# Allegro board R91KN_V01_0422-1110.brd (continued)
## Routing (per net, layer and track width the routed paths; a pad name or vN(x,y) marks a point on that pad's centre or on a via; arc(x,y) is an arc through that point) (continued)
M_MAA1: length 107.4
  TOP w0.097: 137.37,69.38 137.53,69.38 137.66,69.25 137.66,69 137.57,68.92 137.22,68.92 137.02,68.72 137.02,68.43 137.18,68.28 137.18,68.07 137.02,67.92 137.02,67.63 137.22,67.43 137.42,67.43 137.64,67.22 137.64,67.22 137.95,66.91 138.36,66.91 138.95,66.32 139.79,66.32 139.91,66.21 139.91,65.06 139.92,65.04 139.92,65.03 139.79,64.91 138.43,64.91 138.2,64.68 138.2,64.54 138.2,64.53 138.2,64.28 138.19,64.28 138.19,64.19 137.8,63.8 v1(137.73,63.8) 137.73,63.73 137.56,63.56 137.1,63.56 136.78,63.24 136.71,63.18 136.22,63.18 135.12,62.35 134.99,62.29 134.91,62.23 133.77,62.23 133.24,62.17 132.7,62.11 132.48,61.89 132.35,61.77 130.93,60.17 130.93,56.99 130.97,56.89 130.97,56.43 v1(131.26,56.13) 131.26,56.74 131.39,56.87 131.48,56.87 131.69,56.66 131.69,56.09 131.81,55.96 132,55.96 132.11,55.85 132.23,55.85 132.3,55.92 132.42,55.92 132.51,55.83 132.51,55.71 132.44,55.64 132.44,55.44 132.5,55.38 132.61,55.38 132.72,55.5 132.85,55.5 132.94,55.41 132.94,55.28 132.77,55.12 132.77,54.99 132.86,54.9 132.98,54.9 133.15,55.07 133.27,55.07 133.36,54.98 133.36,54.86 132.99,54.49 132.99,54.37 133.08,54.28 133.21,54.28 133.61,54.68 133.73,54.68 133.82,54.6 133.82,54.47 133.72,54.37 133.72,54.24 133.72,54.17 133.91,53.98 134.24,53.98 134.43,53.8 134.66,53.8 134.66,53.57 135.83,52.4 136.46,52.4 137.2,51.66 137.86,51.66 137.98,51.54 137.98,51.52 138.08,51.42 138.31,51.42 138.41,51.33 v1(138.41,51.29) ; v1(131.87,50.35) 131.93,50.42 132.49,50.42 132.54,50.37 132.54,50.21 132.62,50.13 132.7,50.13 132.71,50.12 132.75,50.12 132.84,50.21 132.84,50.38 132.93,50.48 133.07,50.48 133.16,50.38 133.16,49.85 133.21,49.8 133.43,49.8 133.55,49.91 133.88,49.91 134.04,49.76 134.04,49.76 134.12,49.68 134.12,49.52 134.5,49.14 134.5,48.96 134.51,48.95 134.51,48.67 134.5,48.67 134.5,48.16 134.51,48.16 134.51,47.88 134.5,47.87 134.5,47.77 134.4,47.67 134.06,47.67 133.92,47.54 133.92,47.35 134.06,47.22 134.16,47.22
  TOP w0.1: v1(134.68,53.8) 134.66,53.8
  TOP w0.2: U1.J20 96.15,55.9 v1(96.52,55.52)
  BOTTOM w0.097: v1(137.73,63.8) 137.61,63.67 136.54,63.67 136.51,63.65 136.19,63.65 135.95,63.88 135.95,63.94 135.62,64.27 135.62,65.43 135.09,65.97 135.09,68.14 134.51,68.72 134.51,68.72 134.31,68.92 133.98,68.92 133.85,69.04 133.85,69.24 133.98,69.36 134.16,69.36 U402.P7 ; 137.37,47.22 137.37,47.17 137.48,47.06 137.54,47.06 137.55,47.05 137.72,47.05 137.82,47.15 137.82,47.36 137.84,47.38 137.84,47.39 137.94,47.49 137.94,47.75 137.81,47.87 137.71,47.87 137.51,47.67 137.22,47.67 137.02,47.87 137.02,48.96 137.08,49.01 137.08,49.24 136.97,49.35 136.97,49.45 137.05,49.53 137.15,49.53 137.31,49.36 137.43,49.36 137.51,49.43 137.51,49.53 137.38,49.67 137.38,49.79 137.46,49.88 137.59,49.88 137.71,49.75 137.84,49.75 137.93,49.84 137.93,49.97 137.8,50.09 137.8,50.22 137.89,50.3 138.01,50.3 138.14,50.18 138.26,50.18 138.41,50.32 v1(138.41,51.29) ; v1(134.68,53.8) 134.66,53.8 134.66,53.43 131.87,50.64 v1(131.87,50.35)
  BOTTOM w0.1: 101.51,54.15 101.31,54.15 101.08,54.38 101.08,54.61 100.95,54.73 100.74,54.73 100.62,54.61 100.62,54.38 100.49,54.26 100.3,54.26 100.17,54.38 100.17,54.62 100.05,54.74 99.85,54.74 99.72,54.62 99.72,54.38 99.6,54.26 99.38,54.26 99.32,54.2 98.98,54.2 98.4,54.78 96.25,54.78 96.13,54.91 96.13,55.4 96.25,55.52 v1(96.52,55.52)
  BOTTOM w0.2: v1(131.26,56.13) 131.26,56.14 131.08,56.14 130.78,55.84 130.01,55.84 128.03,53.85 128.02,53.85 127.93,53.76 127.54,53.76 127.45,53.85 124.69,53.85 124.37,54.17 104.39,54.17 104.27,54.29 104.27,54.97 103.9,55.34 103.73,55.34 103.6,55.22 103.6,54.28 103.48,54.16 103.09,54.16 102.97,54.28 v4(102.97,54.7) 102.97,55.26 102.84,55.38 102.68,55.38 102.26,54.96 102.26,54.27 102.14,54.15 101.51,54.15
M_MAA2: length 111.7
  TOP w0.097: v1(131.51,66.61) 131.53,66.59 131.57,66.59 131.73,66.43 133.53,66.43 133.96,66.86 133.96,67.08 134.51,67.62 134.51,68.72 134.31,68.92 133.82,68.92 133.7,69.04 133.7,69.23 133.71,69.23 133.71,69.52 133.7,69.52 133.7,69.71 133.82,69.83 134.04,69.83 134.16,69.71 U401.P3 ; 137.37,47.22 137.34,47.22 137.22,47.33 137.22,47.49 137.35,47.62 137.48,47.62 137.69,47.41 137.81,47.41 138,47.6 138,47.7 137.82,47.87 137.82,48.16 138,48.34 138,48.49 137.82,48.67 137.82,48.96 137.88,49.02 137.88,49.03 137.97,49.12 137.98,49.12 138.02,49.16 138.22,49.16 138.3,49.23 138.62,49.23 138.82,49.44 138.82,49.52 139.46,50.15 139.46,50.96 139.83,51.33 140.23,51.33 140.32,51.42 140.32,51.57 140.23,51.66 139.61,51.66 139.52,51.76 139.52,51.89 139.61,51.98 140.27,51.98 140.32,52.03 140.32,52.22 140.27,52.27 139.5,52.27 v1(139.4,52.38) 139.4,52.4 139.53,52.52 139.82,52.52 139.91,52.61 139.91,52.73 139.82,52.82 139.36,52.82 139.28,52.9 139.28,53 139.36,53.08 139.78,53.08 139.87,53.17 139.87,53.29 139.78,53.38 139.42,53.38 139.34,53.46 139.34,53.57 139.42,53.65 139.81,53.65 139.9,53.74 139.9,53.85 139.8,53.95 139.16,53.95 139.03,54.08 139.03,54.11 139.27,54.35 139.27,54.48 139.18,54.57 139.06,54.57 138.82,54.33 138.69,54.33 138.61,54.41 138.61,54.54 138.85,54.78 138.85,54.9 138.76,54.99 138.63,54.99 138.39,54.75 138.28,54.75 138.18,54.84 138.18,54.93 138.31,55.05 138.31,55.06 138.41,55.17 138.41,55.27 138.34,55.34 138.23,55.34 138.06,55.17 137.85,55.17 137.76,55.26 137.76,55.39 137.78,55.41 137.78,55.53 137.69,55.62 137.56,55.62 137.55,55.6 137.42,55.6 137.33,55.69 137.33,55.81 137.35,55.83 137.35,55.95 137.26,56.04 137.14,56.04 137.12,56.02 137,56.02 136.91,56.11 136.91,56.23 136.93,56.25 136.93,56.38 136.84,56.47 136.55,56.47 v1(135.84,57.19) 135.84,57.47 135.44,57.87 135.44,57.99 134.87,58.57 134.87,59.67 v1(134.85,59.69)
  TOP w0.17: U1.H23 97.15,53.8 97.35,54 v1(97.35,54.3)
  BOTTOM w0.097: v1(139.4,52.38) 138.61,52.38 v4(138.5,52.27) 138.5,52.27 138.49,52.27 137.58,51.35 135.53,51.35 135.45,51.25 135.14,50.95 135.08,50.8 134.83,47.88 134.16,47.22 ; 137.37,69.38 138.01,69.78 139.84,69.78 140.8,68.81 140.8,61.83 138.38,59.41 135.96,59.41 135.89,59.49 135.05,59.49 v1(134.85,59.69) 135.04,59.88 135.57,59.88 135.8,60.11 135.8,60.45 135.51,60.73 135.4,60.73 131.51,64.62 v1(131.51,66.61)
  BOTTOM w0.1: 100.44,53.77 100.4,53.8 96.81,53.8 96.72,53.9 96.72,54.2 96.81,54.3 v1(97.35,54.3)
  BOTTOM w0.2: v1(135.84,57.19) 135.73,57.28 135.64,57.28 135.18,57.14 134.85,57.08 134.7,57.03 134.33,56.98 133.03,55.67 133.03,55.67 131.91,55.67 131.59,55.35 131.24,55.35 131.06,55.17 131,55.17 131,55.17 130.29,55.17 128.34,53.21 128.34,53.21 128.31,53.19 128.3,53.19 128.21,53.09 127.26,53.09 127.17,53.19 124.41,53.19 124.39,53.2 124.34,53.2 124.07,53.46 100.74,53.46 100.44,53.77
M_MAA3: length 114.4
  TOP w0.097: v1(137.79,64.5) 137.78,64.5 137.63,64.27 137.25,63.89 137,63.78 136.62,63.41 136.13,63.41 135,62.55 134.85,62.49 134.83,62.47 133.76,62.47 v1(132.33,62.3) 130.69,60.25 130.69,56.96 130.7,56.92 130.73,56.84 130.73,56.66 130.71,56.63 130.71,56.19 v1(131.52,54.9) 131.75,54.9 131.88,55.02 131.88,55.23 131.75,55.36 131.55,55.36 131.44,55.47 131.44,55.62 131.55,55.73 131.9,55.73 132.15,55.48 132.15,55.02 132.28,54.9 132.5,54.9 132.59,54.81 132.59,54.67 132.5,54.58 132.09,54.58 131.98,54.47 131.98,54.34 132.11,54.21 132.79,54.21 132.92,54.09 132.92,54.08 133.18,53.82 133.32,53.82 v1(133.41,53.91) 133.58,53.75 134.15,53.75 135.73,52.16 136.06,52.16 136.41,52.16 137.12,51.45 137.7,51.45 137.81,51.35 138,51.15 138,51.12 138.04,51.09 138.04,50.96 138.11,50.89 138.76,50.89 138.83,50.82 138.83,50.73 138.76,50.66 138.42,50.66 138.37,50.61 138.37,50.47 138.43,50.41 138.62,50.41 138.69,50.34 138.69,50.23 138.29,49.83 138.2,49.83 138.12,49.92 138.12,49.92 138,50.04 137.87,50.04 137.8,49.98 137.8,49.95 137.7,49.84 137.7,49.72 137.34,49.36 136.92,49.36 136.82,49.27 136.82,47.95 137.02,47.75 137.02,46.89 137.15,46.77 137.48,46.77 137.61,46.89 137.61,46.93 137.73,47.05 137.84,47.05 138.02,46.87 138.5,46.87 138.63,46.75 138.63,46.56 138.62,46.56 138.62,46.27 138.63,46.27 138.63,46.14 138.5,46.02 137.84,46.02 137.71,46.14 137.71,46.29 137.84,46.41 U202.N2 ; v1(131.26,69.91) 131.44,69.73 133.07,69.73 133.37,70.03 133.37,70.17
  TOP w0.17: v1(97.35,53.4) 97.65,53.4 97.75,53.5 U1.G23
  BOTTOM w0.097: U402.N2 138.08,70.09 137.96,70.03 137.79,69.94 137.49,69.81 137.24,69.73 137.02,69.52 137.02,67.63 137.03,67.63 137.22,67.43 137.29,67.43 137.29,67.37 138.39,66.27 138.39,66.03 138.39,66.03 138.39,65.63 138.39,65.63 138.39,65.47 138.27,65.35 138.27,65.35 137.79,64.88 v1(137.79,64.5) ; v1(131.26,69.91) 130.95,69.91 130.13,69.09 130.13,68.62 130.34,68.41 130.34,67.45 130.21,67.31 130.21,66.89 130.48,66.62 130.48,65.81 130.28,65.61 130.28,64.31 131.68,62.91 131.76,62.91 131.99,62.68 131.99,62.41 132.1,62.3 v1(132.33,62.3) ; v1(133.41,53.91) 133.39,53.9 132.07,53.9 131.75,53.56 131.5,53.31 131.5,53.31 131.37,53.19 131.37,52.23 130.61,51.48 129.84,50.7 129.84,50.53 129.62,50.31 129.62,49.97 130.1,49.48 130.1,49.03 130.44,48.69 130.44,48.38 130.31,48.24 130.31,47.7 130.44,47.57 130.44,46.82 130.95,46.31 131.29,46.31 131.52,46.55 131.52,46.57 131.81,46.87 133.7,46.87 133.82,46.74 133.82,46.56 133.82,46.56 133.82,46.27 133.99,46.1 133.99,45.96 133.9,45.86 133.61,45.86 133.51,45.96 133.47,45.96 133.37,46.06 133.37,46.41
  BOTTOM w0.2: v1(97.35,53.4) 97.48,53.53 99.48,53.53 99.7,53.31 99.7,52.63 99.79,52.55 100.33,52.55 100.49,52.7 v4(100.49,52.86) 100.49,53.01 100.58,53.1 101.02,53.1 101.14,52.98 101.14,52.67 101.27,52.55 101.84,52.55 102.14,52.84 102.14,53 102.26,53.12 114.39,53.12 114.49,53.02 114.49,52.85 114.59,52.76 114.99,52.76 115.09,52.85 115.09,53.02 115.19,53.12 115.59,53.12 115.69,53.02 115.69,52.85 115.79,52.76 116.19,52.76 116.29,52.85 116.29,53.02 116.39,53.12 116.79,53.12 116.89,53.02 116.89,52.85 116.99,52.76 117.4,52.76 117.5,52.85 117.5,53.05 117.58,53.12 118.03,53.12 118.1,53.05 118.1,52.85 118.2,52.76 118.59,52.76 118.69,52.85 118.69,53.02 118.79,53.12 119.19,53.12 119.29,53.02 119.29,52.85 119.39,52.76 119.79,52.76 119.91,52.87 119.91,53.02 120.01,53.12 120.41,53.12 120.51,53.02 120.51,52.87 120.61,52.77 120.99,52.77 121.09,52.87 121.09,53.02 121.19,53.12 121.59,53.12 121.69,53.02 121.69,52.85 121.79,52.76 122.06,52.76 122.18,52.88 122.18,53.01 122.3,53.13 122.67,53.13 122.73,53.07 122.73,52.88 122.85,52.76 123.16,52.76 123.29,52.88 123.29,52.98 123.41,53.1 123.96,53.1 124.2,52.87 124.25,52.87 124.27,52.85 124.38,52.85 124.38,52.85 127.03,52.85 127.12,52.76 128.34,52.76 128.44,52.85 128.45,52.85 130.44,54.84 131.45,54.84 131.52,54.9 v1(131.52,54.9)
M_MAA4: length 116.2
  TOP w0.097: U401.P8 138.13,69.34 138.13,69.09 138.25,68.97 140.39,68.97 141.06,68.31 141.06,65.95 141.5,65.51 141.5,61.44 141.5,61.44 141.5,61.24 141.5,61.24 141.5,61.11 141.37,60.98 141.24,60.98 141.24,60.98 v4(139.37,60.98) 137.97,60.98 137.84,60.86 v1(137.84,60.42) 137.81,60.39 137.81,59.88 137.72,59.78 137.41,59.78 137.28,59.66 137.28,59.51 137.37,59.42 138.05,59.42 138.05,59.41 138.28,59.41 138.38,59.32 138.38,59.21 138.29,59.12 137.37,59.12 137.28,59.03 137.28,58.91 137.37,58.82 138.3,58.82 138.39,58.73 138.39,58.03 138.26,57.91 137.41,57.91 137.28,57.78 137.28,57.47 137.34,57.41 137.37,57.41 137.74,57.03 137.74,56.5 138.06,56.18 139.43,56.18 v1(140.03,55.58) ; v1(131.27,47.34) 131.75,46.87 133.01,46.87 133.37,47.22
  TOP w0.1: v3(137.28,57.41) 137.34,57.41
  TOP w0.17: v1(98.1,54.3) 98.12,53.62 98.02,53.45 97.99,53.38 U1.G24
  BOTTOM w0.097: v1(137.84,60.42) 137.7,60.27 136.8,60.27 135.88,61.2 135.6,61.2 132.04,64.75 132.04,66.24 132.2,66.4 132.2,66.8 131.93,67.06 131.93,67.41 132.11,67.59 132.11,67.8 132.42,68.12 132.67,68.12 132.91,68.36 132.91,69.44 133.03,69.57 133.24,69.57 133.37,69.44 133.37,69.38 ; 138.16,47.22 138.16,46.87 138.27,46.76 138.47,46.76 138.63,46.92 138.63,47.07 138.62,47.07 138.62,47.36 138.62,47.36 138.62,47.48 138.77,47.63 139.37,47.63 139.39,47.62 139.72,47.62 139.74,47.63 139.99,47.63 140.08,47.54 140.08,46.45 140.21,46.33 140.47,46.33 140.6,46.45 140.6,47.38 140.94,47.73 140.94,51.67 140.97,51.69 140.97,52.4 141.59,53.02 141.59,53.48 141.68,53.56 142.07,53.56 142.16,53.65 142.16,53.78 142.07,53.86 141.68,53.86 141.59,53.95 141.59,54.08 141.68,54.16 142.05,54.16 142.14,54.25 142.14,54.38 142.05,54.46 141.68,54.46 141.59,54.55 141.59,54.99 140.97,55.6 140.05,55.6 v1(140.03,55.58) 140.03,55.58 136.93,55.58 135.73,54.38 135.73,54.17 132.44,50.87 132.44,50.28 131.59,49.44 131.59,49.18 131.42,49.01 131.42,47.49 v1(131.27,47.34)
  BOTTOM w0.1: 100.75,54.02 100.32,54.02 100.31,54 98.94,54 v1(98.1,54.3)
  BOTTOM w0.2: v3(137.28,57.41) 137.22,57.38 136.95,57.3 136.37,57.3 136.03,57.63 135.65,57.63 135.1,57.47 134.77,57.4 134.62,57.36 134.18,57.29 133.06,56.17 131.94,56.17 131.45,55.69 131.1,55.69 130.92,55.51 130.86,55.51 130.86,55.51 130.16,55.51 128.17,53.52 128.16,53.52 128.06,53.42 127.41,53.42 127.31,53.52 124.54,53.52 124.53,53.53 124.47,53.53 124.21,53.8 101.29,53.8 100.75,54.02
M_MAA5: length 114.1
  TOP w0.097: 133.37,69.38 133.03,69.16 132.78,69.11 132.7,69.05 132.17,68.94 131.84,68.94 131.8,68.98 v1(131.44,68.98) ; 138.16,47.22 138.16,47.42 138.2,47.45 138.2,47.53 138.32,47.66 138.55,47.66 138.68,47.53 138.68,47.41 138.62,47.36 138.62,47.07 138.64,47.06 138.64,47.02 138.79,46.87 138.87,46.87 138.92,46.81 140.51,46.81 140.61,46.91 140.61,47.04 140.51,47.14 140.06,47.14 139.97,47.24 139.97,47.38 139.96,47.39 140.06,47.49 140.87,47.49 140.96,47.58 140.96,47.7 140.87,47.79 140.08,47.79 140,47.88 140,48 140.08,48.09 140.87,48.09 140.96,48.18 140.96,54.21 140.87,54.3 140.4,54.3 140.31,54.39 140.31,54.51 140.4,54.6 140.87,54.6 140.96,54.69 140.96,54.92 v1(140.79,55.09) 140.96,55.26 140.96,56.41 140.75,56.62 140.05,56.62 139.95,56.72 139.95,57.09 139.83,57.2 139.67,57.2 139.55,57.09 139.55,56.72 139.45,56.62 v1(138.19,56.62) 138.62,57.05 138.62,59.41 v1(138.22,59.81)
  TOP w0.17: v1(97.35,52.6) U1.H24
  BOTTOM w0.097: U402.P2 138.16,69.24 138.28,69.12 138.53,69.12 138.69,68.97 140.18,68.97 140.31,68.85 140.31,68.64 140.18,68.51 140.03,68.51 139.94,68.42 139.94,68.3 140.03,68.21 140.39,68.21 140.48,68.12 140.48,68 140.39,67.91 140.2,67.91 140.11,67.82 140.11,67.7 140.2,67.61 140.39,67.61 140.48,67.52 140.48,67.4 140.39,67.31 139.94,67.31 139.85,67.22 139.85,67.1 139.94,67.01 140.39,67.01 140.48,66.92 140.48,66.72 140.39,66.64 140.07,66.64 139.98,66.55 139.98,66.42 140.07,66.34 140.39,66.34 140.48,66.25 140.48,66.12 140.39,66.04 140.07,66.04 139.98,65.95 139.98,65.82 140.07,65.74 140.39,65.74 140.48,65.65 140.48,61.91 138.38,59.81 v1(138.22,59.81) 136.71,60.04 135.6,60.97 135.5,60.97 131.85,64.62 131.85,66.37 131.91,66.44 131.91,66.78 131.91,66.79 131.76,66.95 131.69,67.06 131.51,67.25 131.42,67.4 131.42,67.92 131.44,67.93 v1(131.44,68.98) ; v1(140.79,55.09) 136.77,55.09 136.35,54.67 136.35,54.43 132.68,50.76 132.68,50.23 131.94,49.49 131.94,49.17 132.22,48.89 132.22,48.67 132.42,48.47 132.59,48.47 132.98,48.08 132.98,47.67 133.37,47.29 133.37,47.22
  BOTTOM w0.2: v1(97.35,52.6) 97.73,52.96 97.92,53.15 98.37,53.15 99,52.59 99.67,52.24 102.01,52.24 102.18,52.41 102.64,52.41 103.02,52.79 114.06,52.79 114.45,52.42 119.71,52.42 119.93,52.42 119.94,52.44 121.63,52.44 121.65,52.42 123.35,52.42 124.08,52.52 124.12,52.52 124.12,52.52 126.63,52.52 127,52.42 127.93,52.42 128.48,52.42 130.67,54.23 130.73,54.29 130.74,54.29 130.89,54.44 131.02,54.44 131.03,54.45 131.61,54.45 131.73,54.5 131.79,54.54 v4(132.51,54.97) 133.54,55.58 134.36,56.18 134.47,56.25 134.56,56.28 136.16,56.5 137.19,56.56 v1(138.19,56.62)
M_MAA6: length 115.3
  TOP w0.097: 133.37,48.02 133.39,48.02 133.51,47.89 133.51,47.75 133.51,47.68 133.39,47.56 133.22,47.56 133.11,47.44 132.94,47.44 132.71,47.67 132.34,47.67 132.34,47.66 131.81,47.66 131.73,47.59 131.59,47.59 131.4,47.78 131.4,48.18 131.36,48.22 131.36,48.23 131.08,48.41 130.46,48.41 130.34,48.29 130.34,47.95 130.46,47.82 130.82,47.82 130.94,47.95 v1(130.94,47.98) ; v1(136.77,54.52) 136.77,54.89 136.36,55.3 136.29,55.3 136.29,55.3 136.12,55.3 136.09,55.27 v1(136.06,55.27) 135.83,55.5 135.83,55.82 135.8,55.85 135.8,56.26 134.33,57.73 134.33,57.94 134.22,58.05 v1(134.22,58.73) 133.61,58.73 133.48,58.86 133.48,59.03 133.61,59.16 134.49,59.16 134.56,59.23 134.56,59.34 134.49,59.41 133.65,59.41 133.52,59.54 133.52,59.85 133.94,60.26 134.09,60.26 134.22,60.39 134.22,60.55 134.57,60.89 135.84,60.89 136.44,61.5 137.16,61.5 137.16,61.51 137.39,61.51 v1(137.41,61.48) 138.34,61.48 138.47,61.61 138.47,61.67 138.59,61.8 139.74,61.8 139.86,61.67 139.86,61.47 140.09,61.24 140.1,61.24 140.1,61.22 141,61.22 141.26,61.48 141.26,65.41 140.83,65.85 140.83,67.88 140.53,68.17 138.88,68.17 138.48,68.58 U401.R8
  TOP w0.17: v1(96.45,57.9) 95.94,57.9 95.82,57.77 95.82,57.33 95.94,57.2 U1.J19
  BOTTOM w0.097: v1(136.06,55.27) 135.99,55.21 135.99,54.97 135.22,54.2 134.5,54.2 134.28,53.98 134.28,53.4 131.57,50.69 131.57,50.69 131.45,50.57 131.45,49.58 131.22,49.34 131.22,48.25 v1(130.94,47.98) ; 133.37,68.58 133.27,68.58 133.15,68.7 133.15,68.9 133.27,69.03 133.57,69.03 133.75,68.84 133.75,68.34 133.63,68.22 133.15,68.22 133.02,68.09 133.02,67.78 132.91,67.67 132.91,67.64 132.73,67.45 132.73,67.07 132.47,66.8 132.47,66.28 132.24,66.06 132.24,64.88 135.62,61.5 136.79,61.5 136.8,61.48 v1(137.41,61.48) ; U201.R8 138.16,47.96 138.29,47.84 138.47,47.84 138.6,47.96 138.6,48.29 138.72,48.41 140.43,48.41 140.71,48.7 140.71,52.47 141.29,53.06 141.29,54.57 141.17,54.7 140.97,54.7 140.85,54.57 140.85,54.47 140.72,54.34 140.58,54.34 140.49,54.43 140.49,54.65 140.41,54.73 140.28,54.73 140.19,54.65 140.19,54.43 140.11,54.34 139.98,54.34 139.89,54.43 139.89,54.65 139.81,54.73 139.68,54.73 139.59,54.65 139.59,54.43 139.51,54.34 139.27,54.34 138.93,54.68 136.93,54.68 v1(136.77,54.52)
  BOTTOM w0.1: 105.35,57.17 101.39,57.17 100.83,57.73 100.16,57.73 100.15,57.75 97.89,57.75 97.52,57.38 96.67,57.38 96.58,57.29 96.58,57.15 96.46,57.02 96.45,57.02 96.1,57.02 96.09,57.02 95.66,57.02 95.54,57.15 95.54,57.44 95.75,57.65 95.75,57.8 95.85,57.9 v1(96.45,57.9)
  BOTTOM w0.2: v1(134.22,58.73) 134.22,58.76 133.96,58.76 133.49,58.29 133.08,58.29 132.14,57.35 132.14,57.35 130.76,57.35 130.37,56.95 130.34,56.95 130.3,56.91 128.5,56.91 127.62,56.03 106.49,56.03 105.35,57.17
M_MAA7: length 116.6
  TOP w0.097: v1(137.19,60.69) 137.11,60.69 137.07,60.65 136.44,60.65 136.15,60.37 135.6,60.37 135.51,60.28 v1(135.4,60.28) 135.4,59.99 136.04,59.35 136.04,58.62 136.66,58 v1(136.66,57.98) 136.59,57.91 136.59,57.31 138.01,55.9 138.44,55.9 138.7,55.64 138.82,55.64 139.12,55.94 139.23,55.94 139.31,55.86 139.31,55.76 139.03,55.48 139.03,55.31 139.12,55.22 139.25,55.22 139.42,55.4 139.55,55.4 139.64,55.31 139.64,55.18 139.46,55.01 139.46,54.88 139.55,54.79 139.67,54.79 140.05,55.18 140.17,55.18 140.26,55.09 140.26,54.96 139.88,54.58 139.88,54.46 140.6,53.74 140.6,53.66 140.61,53.65 140.61,53.63 140.72,53.52 140.72,51.02 140.63,50.93 139.99,50.93 139.91,50.84 139.91,50.72 139.99,50.63 140.63,50.63 140.72,50.54 140.72,50.42 140.63,50.33 140,50.33 139.91,50.24 139.91,50.12 140,50.03 140.63,50.03 140.72,49.94 140.72,49.82 140.63,49.73 139.85,49.73 139.76,49.64 139.76,49.52 139.85,49.43 140.63,49.43 140.72,49.34 140.72,49.22 140.63,49.13 140.25,49.13 140.16,49.04 140.16,48.92 140.25,48.83 140.65,48.83 140.72,48.76 140.72,48.54 140.6,48.41 138.88,48.41 138.48,48.02 U202.R2 ; 133.37,68.58 132.93,68.14 131.56,68.14 131.32,68.37 130.99,68.37 130.96,68.4 130.7,68.4 130.54,68.57 130.53,68.57 130.41,68.69 130.16,68.94 130.16,69.28 130.29,69.41 130.48,69.41 130.74,69.15 v1(130.74,68.95)
  TOP w0.1: v1(140.56,53.63) 140.61,53.63
  TOP w0.17: v1(95.35,57.81) U1.K19
  BOTTOM w0.097: v1(130.74,68.95) 130.51,68.72 130.51,68.58 130.68,68.4 130.96,68.4 131.22,68.14 131.22,66.88 131.12,66.78 131.12,66.42 131.14,66.4 131.14,65.57 130.91,65.35 130.91,64.89 133.18,62.63 133.18,62.34 133.72,61.79 133.72,61.38 134.23,60.88 134.88,60.88 135.12,60.64 135.12,60.56 v1(135.4,60.28) ; 133.37,48.02 133.37,48.24 133.02,48.59 133.02,50.77 135.99,53.74 137.53,53.74 137.61,53.82 140.36,53.82 v1(140.56,53.63) ; v1(137.19,60.69) 137.41,60.69 137.61,60.89 137.69,60.89 138.33,61.53 v4(138.97,61.53) 139.42,61.53 140.22,62.32 140.22,62.45 140.13,62.54 139.75,62.54 139.66,62.63 139.66,62.75 139.75,62.83 140.16,62.83 140.25,62.92 140.25,63.04 140.16,63.12 139.83,63.12 139.75,63.21 139.75,63.33 139.83,63.41 140.16,63.41 140.25,63.5 140.25,63.62 140.16,63.71 139.83,63.71 139.75,63.79 139.75,63.91 139.83,64 140.16,64 140.25,64.08 140.25,64.2 140.16,64.29 139.83,64.29 139.75,64.37 139.75,64.49 139.83,64.58 140.16,64.58 140.25,64.66 140.25,64.78 140.16,64.87 139.83,64.87 139.75,64.95 139.75,65.08 139.83,65.16 140.16,65.16 140.25,65.25 140.25,65.37 140.16,65.45 139.83,65.45 139.75,65.54 139.75,66.72 139.55,66.92 139.26,66.92 139.03,67.15 139.03,67.29 138.88,67.43 138.82,67.43 138.62,67.63 138.62,67.92 138.82,68.12 138.84,68.12 138.84,68.23 138.82,68.23 138.62,68.43 138.62,68.72 138.5,68.85 138.37,68.85 138.16,68.65 U402.R2
  BOTTOM w0.1: 102.47,57.49 102.38,57.41 101.43,57.41 100.91,57.93 100.25,57.93 100.23,57.95 98.15,57.95 97.7,58.4 96.14,58.4 95.84,58.1 95.77,58.1 95.48,57.81 v1(95.35,57.81)
  BOTTOM w0.2: 102.47,57.49 105.46,57.49 106.58,56.37 127.41,56.37 128.28,57.24 130.16,57.24 130.2,57.28 130.22,57.28 130.62,57.69 132,57.69 132.94,58.62 133.35,58.62 133.91,59.19 134.44,59.19 134.58,59.04 134.85,59.04 135.45,58.44 136.21,58.44 v1(136.66,57.98)
M_MAA8: length 116.1
  TOP w0.097: 133.37,48.81 133,48.81 132.91,48.91 132.91,48.96 132.77,49.09 132.77,49.5 132.53,49.73 131.1,49.73 v3(130.76,49.4) ; U401.T8 138.09,67.78 137.97,67.9 137.97,68.09 138.09,68.22 138.49,68.22 138.62,68.09 138.62,67.63 138.82,67.42 138.82,67.42 139.03,67.22 139.03,67.15 139.26,66.92 139.78,66.92 139.91,67.05 139.91,67.36 140.1,67.56 140.1,67.63 140.11,67.63 140.11,67.78 140.23,67.9 140.45,67.9 140.57,67.78 140.57,67.44 140.49,67.35 140.41,67.35 140.32,67.26 140.32,67.14 140.41,67.05 140.49,67.05 140.57,66.96 140.57,65.75 141.03,65.29 141.03,61.6 140.91,61.48 140.79,61.48 140.7,61.56 140.7,62.12 140.64,62.18 140.45,62.18 140.4,62.12 140.4,61.56 140.31,61.48 140.19,61.48 140.1,61.56 140.1,61.95 139.97,62.08 137.94,62.08 v1(137.88,62.01) 137.25,62.01 136.97,61.73 136.35,61.73 135.74,61.13 134.47,61.13 133.13,59.79 v1(133.13,59.32) 133.1,59.3 133.1,59.23 133.09,59.21 133.09,58.85 133.86,58.08 134.09,57.85 134.09,57.18 134.26,57.01 134.38,57.01 134.48,57.11 134.6,57.11 134.69,57.02 134.69,56.9 134.59,56.8 134.59,56.67 135.43,55.84 v1(135.43,55.6) 135.43,55.32 136.36,54.38 136.36,54.37 136.37,54.37 136.37,54.36 136.6,54.12 136.97,54.12 137,54.14 v1(137.37,54.14)
  TOP w0.17: U1.J14 96.1,60.8 96.03,60.72 96.03,60.12 96.12,60.02 96.47,60.02 96.57,60.12 v1(96.57,60.29)
  BOTTOM w0.097: v1(137.88,62.01) 137.33,62.01 137.06,61.73 135.72,61.73 135.46,61.99 135.46,62.11 135.61,62.26 135.61,62.38 135.52,62.47 135.4,62.47 135.25,62.33 135.13,62.33 135.04,62.41 135.04,62.54 135.19,62.68 135.19,62.81 135.1,62.9 134.97,62.9 134.83,62.75 134.7,62.75 134.61,62.84 134.61,62.96 134.76,63.11 134.76,63.23 134.67,63.32 134.55,63.32 134.4,63.17 134.28,63.17 134.19,63.26 134.19,63.39 134.34,63.53 134.34,63.66 134.25,63.74 134.12,63.74 133.98,63.6 133.85,63.6 133.77,63.69 133.77,63.81 133.91,63.96 133.91,64.08 133.82,64.17 133.7,64.17 133.55,64.02 133.43,64.02 133.34,64.11 133.34,64.23 133.49,64.38 133.49,64.51 133.4,64.59 133.28,64.59 133.13,64.45 133.01,64.45 132.92,64.54 132.92,64.66 133.06,64.81 133.06,64.93 132.98,65.02 132.85,65.02 132.71,64.87 132.58,64.87 132.44,65.01 132.44,65.22 132.53,65.31 132.87,65.31 132.96,65.39 132.96,65.52 132.87,65.61 132.53,65.61 132.44,65.69 132.44,65.98 132.66,66.2 132.66,66.68 132.96,66.98 132.96,67.41 133.11,67.55 133.11,67.57 133.31,67.78 133.37,67.78 ; U201.T8 138.26,48.72 138.56,48.72 138.62,48.78 138.62,49.03 139.26,49.67 139.75,49.67 140.09,49.33 140.09,49.07 140.2,48.96 140.36,48.96 140.48,49.07 140.48,52.57 141.06,53.15 141.06,53.73 140.73,54.06 139.22,54.06 138.84,54.45 138.56,54.45 138.47,54.36 138.47,54.14 138.38,54.06 138.26,54.06 138.17,54.14 138.17,54.36 138.08,54.45 137.67,54.45 v1(137.37,54.14) ; v1(135.43,55.6) 135.26,55.6 135.15,55.48 135.15,55.3 135.27,55.18 135.53,55.18 135.65,55.05 135.65,54.97 135.54,54.86 135.44,54.86 135.31,54.73 135.31,54.65 135.22,54.55 135.12,54.55 135.01,54.65 135.01,54.95 134.93,55.04 134.81,55.04 134.72,54.95 134.72,54.5 134.65,54.43 134.46,54.43 134.39,54.5 134.39,54.77 134.29,54.88 134.2,54.88 134.04,54.73 134.04,53.53 131.23,50.72 131.23,49.86 v3(130.76,49.4)
  BOTTOM w0.1: v1(96.57,60.29) 96.67,60.29 97.64,61.26 97.64,61.58 97.88,61.82 98.34,61.82 98.69,61.47
  BOTTOM w0.2: v1(133.13,59.32) 133.13,59.3 133,59.18 132.53,59.18 132.39,59.04 132,59.04 131.78,59.27 131.78,59.52 131.68,59.61 130.53,59.61 130.41,59.48 130.41,59.11 130.28,58.98 109.21,58.98 107.3,60.9 106.78,60.9 106.65,60.77 106.65,60.53 106.56,60.44 106.14,60.44 106.02,60.56 106.02,60.8 105.89,60.92 105.34,60.92 105.21,60.8 105.21,60.56 105.09,60.44 104.61,60.44 104.47,60.58 104.47,60.86 104.35,60.98 103.79,60.98 103.66,60.85 103.66,60.56 103.54,60.44 102.95,60.44 102.83,60.56 102.83,60.92 102.73,61.02 v4(102.73,61.41) 102.72,61.4 102.28,61.4 102.22,61.47 102.09,61.47 102.07,61.49 101.69,61.49 101.67,61.47 98.69,61.47
M_MAA9: length 110.1
  TOP w0.097: 137.37,48.02 137.48,48.02 137.61,48.14 137.61,48.37 137.51,48.47 137.12,48.47 137.02,48.57 137.02,48.96 137.23,49.16 137.43,49.16 137.78,49.52 137.81,49.52 137.86,49.56 138.06,49.56 138.13,49.63 138.43,49.63 138.43,49.68 139.06,50.31 139.06,51.01 138.97,51.09 138.91,51.09 138.83,51.17 138.83,51.28 138.91,51.36 138.93,51.36 139.06,51.48 139.06,51.6 138.93,51.73 138.18,51.73 138.07,51.83 138.07,51.84 137.96,51.95 137.72,51.95 137.62,52.05 v1(137.62,52.05) 137.45,51.89 137.25,51.89 136.94,52.2 136.94,52.2 136.82,52.31 136.82,52.37 136.56,52.63 136.13,52.63 136.06,52.71 136.06,52.8 136.12,52.87 136.12,53.02 136.03,53.1 135.92,53.1 135.72,52.9 135.61,52.9 135.52,52.99 135.52,53.14 135.71,53.34 135.82,53.45 135.82,53.52 135.73,53.62 135.57,53.62 135.31,53.36 135.2,53.36 135.06,53.5 135.06,53.62 135.19,53.74 135.19,53.86 134.84,54.2 134.36,54.2 134.34,54.22 134.21,54.22 134.13,54.3 134.13,54.36 134.23,54.46 134.31,54.45 134.41,54.55 134.41,54.63 134.31,54.74 134.19,54.74 134.16,54.71 134.04,54.71 133.95,54.8 133.95,54.92 133.98,54.95 133.98,55.07 133.81,55.24 133.44,55.24 132.46,56.22 132.3,56.22 132.27,56.19 132.11,56.19 132,56.3 132,56.46 132.04,56.51 132.04,56.63 131.69,56.98 131.69,57.07 131.61,57.15 131.25,57.15 131.16,57.24 131.16,57.37 131.25,57.45 131.67,57.45 131.74,57.52 131.74,57.69 131.67,57.76 131.24,57.76 131.16,57.84 131.16,58 131.24,58.08 131.31,58.08 131.41,58.18 131.41,58.34 131.34,58.41 131.24,58.41 131.16,58.5 131.16,59.08 131.24,59.16 v1(131.32,59.16) 131.34,59.17 131.34,60.28 132.01,61.03 132.68,61.59 v1(132.93,61.73) 133.07,61.82 133.59,61.98 133.75,61.99 134.75,61.99 134.76,62 134.99,62 135.1,62.09 135.24,62.14 136.3,62.95 136.8,62.95 136.81,62.95 136.82,62.95 137.19,63.33 137.75,63.33 137.83,63.41 138.27,63.41 138.36,63.51 138.36,64.01 138.45,64.09 138.57,64.09 138.66,64.01 138.66,63.51 138.75,63.41 138.96,63.41 139.08,63.53 139.08,64.39 138.96,64.51 v1(138.6,64.51) ; U401.R3 134.06,68.67 133.84,68.67 133.72,68.55 133.72,67.61 133.54,67.43 133.39,67.43 132.97,67.01 132.97,67 132.6,66.63 131.97,66.63 131.91,66.68 131.91,66.8 131.73,66.98 131.73,67.03 131.72,67.03 131.51,67.24 131.31,67.24 131.19,67.36 131.19,67.42 131.06,67.55 130.98,67.55 130.98,67.55 130.61,67.55 130.37,67.78 130.18,67.78 130.05,67.66 130.05,67.56 129.69,67.2 129.69,66.99 129.82,66.86 130.23,66.86 130.4,66.7 131.03,66.7 131.15,66.82 131.15,67.03 131.03,67.15 130.6,67.15 130.6,67.14 v1(130.61,67.14)
  TOP w0.17: U1.K14 95.09,60.8 95,60.7 95,60.3 95.09,60.2 v1(95.25,60.2)
  BOTTOM w0.097: v1(137.62,52.05) 137.12,51.56 135.44,51.55 134.98,51.06 134.88,50.86 134.81,49.95 134.71,48.88 U201.R3 ; v1(138.6,64.51) 138.6,64.26 138.72,64.14 139.23,64.14 139.35,64.26 139.35,64.29 139.13,64.51 139.13,64.64 139.35,64.87 139.35,66.03 138.02,67.36 138.02,67.36 137.82,67.56 137.82,67.92 137.97,68.06 137.97,68.28 137.85,68.41 137.82,68.43 137.82,68.72 138,68.89 138,69.05 137.97,69.08 137.97,69.09 137.83,69.23 137.7,69.23 137.51,69.03 137.34,69.03 137.22,68.91 137.22,68.69 137.34,68.58 137.37,68.58 ; v1(132.93,61.73) 132.9,61.73 132.78,61.86 132.78,62.47 131.31,63.94 130.98,63.94 130.51,64.41 130.51,65.13 130.51,65.13 130.51,65.51 130.71,65.71 130.71,65.71 130.72,65.99 130.72,66 130.72,66.25 130.72,66.25 130.72,66.72 130.63,66.81 130.63,67.14 v1(130.61,67.14)
  BOTTOM w0.1: 98.78,61.05 98.25,61.05 98.22,61.02 97.88,61.02 97.85,61.05 97.72,61.05 96.97,60.3 96.97,60.12 96.66,59.8 96.55,59.8 96.19,59.45 95.21,59.45 95.11,59.55 95.11,59.7 95.21,59.8 96.05,59.8 96.15,59.9 96.15,60.23 96.05,60.34 95.8,60.34 95.7,60.44 95.7,60.51 95.6,60.61 95.14,60.61 95.04,60.51 95.04,60.35 95.19,60.2 v1(95.25,60.2)
  BOTTOM w0.2: 98.78,61.05 98.88,61.15 101.31,61.15 101.43,61.02 101.43,60.85 101.69,60.59 102.07,60.59 102.13,60.66 102.41,60.66 102.53,60.53 102.53,60.44 102.83,60.14 102.89,60.14 102.92,60.1 106.61,60.1 106.85,59.87 107.09,59.87 107.35,60.12 107.6,60.12 107.77,59.95 107.77,59.7 107.52,59.44 107.52,59.2 107.64,59.07 107.97,59.07 108.15,59.24 108.47,59.24 109.07,58.65 130.42,58.65 130.43,58.65 130.74,58.97 130.74,59.02 130.88,59.16 v1(131.32,59.16)
M_MAA10: length 107.4
  TOP w0.097: 137.37,71.78 137.37,71.88 137.49,72 137.75,72 137.83,71.92 137.82,71.92 137.82,71.63 138,71.45 138,71.31 137.88,71.19 137.64,71.19 137.51,71.32 137.01,71.32 136.88,71.19 136.88,71.19 136.87,71.17 136.87,69.97 136.43,69.52 136.43,67.08 136.51,67 136.51,66.08 136.38,65.95 v1(136.35,65.95) 136.32,65.92 136.32,65.87 136.24,65.79 135.78,65.79 134.15,64.16 130.17,64.16 128.96,62.95 128.57,62.95 128.31,62.69 128.31,62.25 128.44,62.13 128.82,62.13 128.9,62.04 128.9,61.89 128.82,61.81 128.41,61.81 128.31,61.72 128.31,61.59 128.41,61.5 128.8,61.5 128.9,61.4 128.9,61.04 128.74,60.88 128.67,60.88 128.57,60.98 128.57,61.17 128.5,61.24 128.39,61.24 128.32,61.17 128.32,60.99 128.2,60.87 127.92,60.87 127.67,61.12 127.62,61.07 127.62,60.41 127.71,60.41 127.93,60.19 127.93,59.87 127.88,59.81 128.24,59.81 128.29,59.77 128.36,59.77 128.52,59.35 128.52,56.23 128.53,56.15 v3(130.16,52.64) 130.35,52.45 133.63,52.45 135.03,51.05 135.04,51.05 135.27,50.82 135.28,50.82 135.43,50.66 v1(135.71,50.66)
  TOP w0.1: 127.67,61.12 v1(127.67,61.14) ; v1(133.75,44.41) 133.77,44.41 134.16,44.81 U202.L7
  TOP w0.17: v1(96.6,63.7) 96.3,63.7 96.15,63.55 U1.J11
  BOTTOM w0.097: v3(130.16,52.64) 129.75,51.9 128.91,50.8 128.91,49.74 129.15,49.01 129.31,48.49 129.46,47.92 129.53,47.67 129.61,46.67 131.35,44.93 132.39,44.5 132.52,44.47 v1(133.75,44.41) ; U402.L7 134.16,71.46 134.71,70.92 134.71,70.78 134.94,70.55 135.28,70.55 135.62,70.89 135.71,70.89 135.97,70.63 135.97,67.07 136.38,66.65 136.38,65.99 v1(136.35,65.95) ; 137.37,44.81 137.03,45.51 136.92,45.71 136.63,46.13 136.13,46.78 135.71,49.07 v1(135.71,50.66)
  BOTTOM w0.1: v1(96.6,63.7) 96.6,63.74 96.47,63.87 96.25,63.87 96.12,63.74 96.12,63.58 96.07,63.53 96.07,63.35 96.17,63.26 96.95,63.26 96.95,63.25 97.03,63.25 97.19,63.41 97.47,63.41 97.59,63.53 97.91,63.53 97.98,63.46 98.32,63.46 98.39,63.53 98.44,63.53 98.76,63.85 98.82,63.85 98.82,63.92 98.85,63.92
  BOTTOM w0.2: 98.85,63.92 99.44,63.92 99.63,64.11 99.88,64.11 100.02,64.25 100.02,64.5 100.2,64.69 101.43,64.69 101.46,64.72 101.84,64.72 101.87,64.69 102.42,64.69 103.4,63.7 111.94,63.7 112.2,63.44 112.2,62.87 112.31,62.76 112.88,62.76 112.98,62.66 113.09,62.66 113.62,62.12 113.75,62.12 113.88,62 113.88,61.5 114,61.37 114.51,61.37 114.62,61.48 v4(114.62,61.77) 114.62,62.02 114.74,62.14 115.16,62.14 115.25,62.04 115.25,61.48 115.38,61.35 115.67,61.35 115.8,61.48 115.8,62 115.92,62.12 116.28,62.12 116.41,62 116.41,61.53 116.53,61.41 116.87,61.41 117,61.53 117,62.03 117.09,62.12 117.56,62.12 117.69,62 117.69,61.45 117.8,61.33 118.12,61.33 118.22,61.43 118.22,62 118.35,62.13 118.66,62.13 118.75,62.03 118.75,61.47 118.85,61.37 119.16,61.37 119.28,61.49 119.28,62.03 119.38,62.13 119.64,62.13 119.77,62.01 119.77,61.5 119.94,61.33 124.87,61.33 124.87,61.33 124.87,61.33 126.04,61.33 126.3,61.07 126.93,61.07 127.13,61.27 127.5,61.27 127.66,61.12 v1(127.67,61.14)
M_MAA11: length 113
  TOP w0.097: U202.R7 134.16,48.3 133.71,48.76 133.71,48.95 133.71,48.96 133.51,49.16 133.22,49.16 133.18,49.12 133.08,49.12 132.97,49.23 132.97,49.58 132.61,49.94 132.33,49.94 132.31,49.95 131.69,49.95 131.53,50.12 v1(130.81,50.12) ; v1(137.88,53.23) 137.26,53.23 136.62,53.87 136.52,53.87 136.13,54.26 136.13,54.28 134.97,55.45 v1(134.75,55.45) 134.76,55.46 134.76,56.01 134.63,56.13 134.56,56.13 134.23,55.8 134.11,55.8 134.02,55.89 134.02,56.02 134.39,56.39 134.39,56.52 134.31,56.6 134.18,56.6 133.83,56.25 133.71,56.25 133.62,56.34 133.62,56.46 133.88,56.73 133.88,56.85 133.72,57.02 133.72,57.88 132.78,58.83 132.78,59.11 132.73,59.15 132.73,59.51 v1(132.54,59.7) 132.75,59.7 132.87,59.82 132.87,60 132.75,60.12 132.23,60.12 132.18,60.17 132.18,60.24 132.53,60.6 132.66,60.6 133.08,60.18 133.19,60.18 134.38,61.37 135.63,61.37 136.41,62.14 136.8,62.14 v1(136.81,62.13) 136.81,62.13 136.88,62.21 136.93,62.21 136.99,62.27 137.57,62.27 137.71,62.41 138.53,62.41 138.62,62.5 138.62,62.89 138.7,62.98 138.83,62.98 138.92,62.89 138.92,62.5 139,62.41 139.13,62.41 139.22,62.5 139.22,62.89 139.3,62.98 139.43,62.98 139.52,62.89 139.52,62.5 139.6,62.41 139.73,62.41 139.82,62.5 139.82,62.89 139.9,62.98 140.03,62.98 140.12,62.89 140.12,62.5 140.2,62.41 140.64,62.41 140.8,62.56 140.8,65.18 140.31,65.67 140.31,66.57 140.15,66.72 139.11,66.72 138.53,67.31 138.12,67.31 137.73,67.7 137.73,68.45 137.6,68.58 137.37,68.58
  TOP w0.17: v1(95.99,62.64) 95.99,62.62 96.15,62.46 U1.J13
  BOTTOM w0.097: v1(136.81,62.13) 136.76,62.09 136.23,62.09 134.5,63.82 134.5,63.95 134.66,64.11 134.66,64.23 134.57,64.32 134.45,64.32 134.29,64.16 134.16,64.16 134.08,64.25 134.08,64.37 134.24,64.53 134.24,64.66 134.15,64.75 134.02,64.75 133.86,64.59 133.74,64.59 133.65,64.67 133.65,64.8 133.81,64.96 133.81,65.08 133.72,65.17 133.6,65.17 133.44,65.01 133.32,65.01 133.16,65.16 133.16,65.37 133.29,65.5 133.66,65.5 133.75,65.58 133.75,65.72 133.66,65.81 132.99,65.81 132.86,65.93 132.86,66.03 132.99,66.15 133.64,66.15 133.73,66.24 133.73,66.36 133.64,66.45 133.05,66.44 132.95,66.54 132.95,66.67 133.16,66.88 133.16,67.2 133.4,67.43 133.68,67.43 133.8,67.56 133.8,67.99 133.93,68.12 134.19,68.12 134.31,68.24 134.31,68.42 134.16,68.56 U402.R7 ; 137.37,48.02 137.37,48.03 137.49,48.16 137.82,48.16 137.88,48.22 137.88,48.61 137.82,48.67 137.82,49.01 137.97,49.15 138.02,49.15 138.02,49.16 138.31,49.16 138.32,49.15 138.45,49.15 139.18,49.87 140.15,49.87 140.28,49.99 140.28,52.36 139.22,53.42 138.08,53.42 v1(137.88,53.23) ; v1(130.81,50.12) 130.85,50.16 130.85,50.72 133.8,53.66 133.8,53.74 133.81,53.75 133.81,54.08 133.8,54.09 133.8,54.82 134.44,55.42 134.75,55.42 v1(134.75,55.45)
  BOTTOM w0.1: v1(95.99,62.64) 95.87,62.64 95.77,62.74 95.77,62.92 95.89,63.05 96.53,63.05 96.53,63.05 96.87,63.05 96.87,63.05 97.11,63.05 97.18,63.12 97.52,63.12 97.59,63.05 97.86,63.05 97.96,63.15
  BOTTOM w0.2: 97.96,63.15 98.41,63.15 98.87,63.6 99.61,63.6 99.71,63.7 100.34,63.7 100.44,63.8 100.44,64.23 100.54,64.33 100.99,64.33 101.09,64.23 101.09,64.16 101.19,64.06 101.22,64.06 101.46,63.81 101.84,63.81 102.09,64.06 102.22,64.06 102.32,63.96 102.32,63.73 102.42,63.63 v4(102.53,63.63) 102.8,63.37 111.72,63.37 111.72,62.33 112.32,62.33 112.64,62.01 112.64,61.57 113.04,61.57 113.05,61.56 113.29,61.56 113.54,61.31 113.61,61.18 113.79,61 121.1,61 121.11,60.99 122.79,60.99 122.8,61 124.73,61 124.73,60.99 125.01,60.99 125.01,61 125.9,61 126.21,60.69 127.86,60.69 128.12,60.95 128.12,61.16 128.23,61.27 128.54,61.27 128.67,61.15 128.67,60.93 128.81,60.79 129.09,60.79 129.21,60.9 129.21,61.18 129.31,61.28 129.53,61.28 129.75,61.52 130.09,61.52 130.22,61.39 130.22,61.33 130.26,61.28 131.5,61.28 132.07,60.72 132.07,60.17 v1(132.54,59.7)
M_MAA12: length 104.6
  TOP w0.097: 131.83,53.11 132.06,52.88 133.79,52.88 135.41,51.26 135.96,51.26 135.96,51.26 135.98,51.26 136.05,51.22 136.51,50.76 v1(136.51,50.63) ; 131.83,53.11 131.81,53.11 131.81,53.13 131.51,53.19 131.13,53.33 131.08,53.38 130.78,53.68 130.78,53.77 130.84,53.83 130.84,53.89 130.71,54.02 130.62,54.02 130.39,53.78 130.25,53.78 130.15,53.88 130.15,54.02 130.37,54.24 130.37,54.36 130.27,54.46 130.16,54.46 130.04,54.34 129.92,54.34 129.88,54.38 129.87,54.38 129.68,54.77 129.51,55.16 129.49,55.2 129.41,55.36 129.26,55.69 128.98,56.28 128.98,60.13 v1(128.98,60.13) 129.18,60.34 129.18,60.66 129.44,60.92 129.84,60.92 130.02,61.1 130.02,61.23 129.94,61.31 129.49,61.31 129.38,61.41 129.38,61.61 129.43,61.65 130.35,61.65 130.45,61.75 130.45,61.9 130.35,62 129.52,62 129.44,62.08 129.44,62.2 129.61,62.37 130.13,62.37 130.3,62.54 130.3,62.85 130.31,62.86 130.31,62.87 130.46,63.01 130.46,63.09 130.31,63.24 130.31,63.3 130.43,63.42 134.38,63.42 134.38,63.42 134.42,63.42 134.43,63.43 134.43,63.43 134.78,63.78 134.78,63.78 135.95,64.95 v1(136.28,64.95) 136.4,65.08 137.21,65.08 137.42,65.29 137.42,65.62 137.38,65.66 137.38,66.06 137.5,66.18 138.25,66.18 138.34,66.27 138.34,66.36 138.22,66.48 137.51,66.48 137.38,66.61 137.38,66.67 137.22,66.83 137.1,66.83 136.94,66.68 136.83,66.68 136.74,66.76 136.74,66.88 136.89,67.03 136.89,67.16 136.63,67.42 136.63,69.44 137.37,70.17 ; 131.83,53.11 v1(131.86,53.11) ; v5(130.01,50.14) 130.03,50.13 130.38,49.18 130.53,49.03 130.68,48.97 131.06,48.72 131.43,48.47 131.74,48.46 131.74,48.47 132.08,48.47 133.51,48.36 133.71,48.16 133.72,47.19 U202.N7
  TOP w0.17: v1(96.7,62.66) 96.59,62.77 96.59,63.06 96.72,63.2 U1.H11
  BOTTOM w0.097: v1(136.28,64.95) 136.37,65.05 136.37,65.37 135.53,66.2 135.53,69.57 135.44,69.66 135.23,69.66 135.03,69.47 134.91,69.47 134.82,69.55 134.82,69.68 135.02,69.88 135.02,70.09 134.96,70.14 134.78,70.14 134.59,70.33 134.29,70.33 134.16,70.21 U402.N7 ; 137.37,46.41 137.43,46.41 137.55,46.29 137.55,46.11 137.43,45.98 137.11,45.98 136.61,46.48 136.4,46.76 136.32,46.87 136.05,48.33 136.05,50.17 v1(136.51,50.63) ; v5(130.01,50.14) 130.07,50.2 130.07,50.6 130.71,51.24 130.71,51.25 131.58,52.12 131.58,52.17 131.67,52.26 131.67,52.79 131.81,52.94 131.81,53.11 v1(131.86,53.11)
  BOTTOM w0.1: 100.46,62.49 100.34,62.61 v4(100.34,62.7) 100.34,62.83 100.27,62.89 99.88,62.89 99.37,62.38 99.03,62.38 98.99,62.42 97.63,62.42 97.47,62.32 97.23,62.32 v1(96.7,62.66)
  BOTTOM w0.2: v1(128.98,60.13) 128.98,60.13 128.88,60.02 126.03,60.02 126,60 125.87,60 125.75,60.12 125.75,60.2 125.62,60.33 125.29,60.33 125.16,60.2 125.16,60.12 125.04,60 124.71,60 124.58,60.12 124.58,60.2 124.46,60.33 124.16,60.33 124.03,60.2 124.03,60.11 123.91,59.99 123.63,59.99 123.51,60.11 123.51,60.2 123.38,60.33 123.07,60.33 122.95,60.2 122.95,60.11 122.83,59.99 122.5,59.99 122.38,60.1 122.38,60.22 122.27,60.33 121.9,60.33 121.78,60.2 121.78,60.11 121.66,59.99 121.07,59.99 120.95,60.11 120.95,60.2 120.82,60.33 120.41,60.33 120.32,60.24 120.32,60.12 120.2,59.99 119.74,59.99 119.62,60.12 119.62,60.2 119.49,60.33 119.1,60.33 118.97,60.2 118.97,60.11 118.85,59.99 118.47,59.99 118.35,60.11 118.35,60.2 118.23,60.33 117.74,60.33 117.62,60.2 117.62,60.11 117.5,59.99 117.02,59.99 116.89,60.11 116.89,60.2 116.77,60.33 116.43,60.33 116.31,60.2 116.31,60.12 116.18,59.99 115.78,59.99 115.65,60.12 115.65,60.23 115.56,60.33 115.22,60.33 115.13,60.23 115.13,60.12 115,59.99 114.73,59.99 114.6,60.12 114.6,60.2 114.48,60.33 114.11,60.33 113.99,60.2 113.99,60.12 113.86,59.99 113.32,59.99 113.19,60.12 113.19,60.63 113.07,60.76 112.76,60.76 112.66,60.66 112.21,60.66 112.12,60.75 112.12,61.08 111.99,61.2 111.72,61.2 111.65,61.13 111.65,60.81 111.52,60.69 111.31,60.69 110.73,60.69 110.41,61.01 110.41,61.01 110.28,61.13 110.09,61.13 109.97,61.01 109.97,60.12 109.95,60.1 109.95,60.09 109.85,59.99 109.63,59.99 109.15,60.47 109.15,60.74 109.3,60.89 109.3,61.17 109.01,61.45 108.73,61.45 108.59,61.31 108.31,61.31 107.69,61.93 107.69,61.93 107.66,61.96 107.38,61.96 107.38,61.96 104.03,61.96 103.32,62.67 102.86,62.67 102.86,62.67 102.12,62.67 102,62.8 102,62.83 101.74,63.09 101.36,63.09 101.1,62.83 101.1,62.83 100.77,62.49 100.46,62.49
M_MAA13: length 108.2
  TOP w0.097: v1(133.56,67.03) 133.56,67.17 U401.T3 ; 137.37,48.81 137.44,48.74 137.5,48.74 137.62,48.87 137.62,49.07 137.87,49.31 137.9,49.31 137.94,49.36 138.14,49.36 138.22,49.43 138.53,49.43 138.62,49.53 138.62,49.6 139.25,50.23 139.25,51.09 139.41,51.25 139.41,51.5 139.25,51.66 139.25,51.83 139.13,51.95 139.05,51.95 138.93,52.08 138.93,53.38 138.81,53.49 v4(138.73,53.49) 138.64,53.49 138.53,53.38 138.53,52.04 138.44,51.95 138.29,51.95 138.16,52.08 138.16,52.69 138.04,52.81 137.78,52.81 137.66,52.69 137.66,52.56 137.55,52.45 137.32,52.45 137.2,52.58 v1(137.2,52.61) 137,52.81 137,53.2 136.53,53.66 136.45,53.66 135.93,54.18 135.93,54.2 135.09,55.05 134.57,55.05 133.98,55.64 133.6,55.64 133.23,56.01 133.23,56.59 133.14,56.68 132.58,56.68 132.5,56.77 132.5,56.89 132.58,56.98 133.42,56.98 133.51,57.08 133.51,57.22 133.42,57.32 132.31,57.32 132.19,57.45 132.19,58.16 132.31,58.28 132.48,58.28 132.6,58.16 132.6,57.8 132.73,57.67 133.06,57.67 133.19,57.8 133.19,57.81 133.11,57.89 133.11,58.21 132.19,59.13 132.19,59.47 131.97,59.68 131.97,60.33 132.78,61.13 132.99,61.13 133.18,60.94 133.52,60.94 133.65,61.07 133.65,61.27 133.55,61.36 133.55,61.48 133.63,61.56 135.53,61.56 136.5,62.53 136.97,62.53 136.98,62.52 137.54,62.52 137.62,62.61 137.87,62.61 138.07,62.81 v1(138.09,62.81)
  TOP w0.1: 133.19,57.81 v3(133.23,57.77)
  TOP w0.17: U1.G20 97.75,55.92 97.84,55.84 98.07,55.84 98.16,55.92 98.16,56.5 98.06,56.6 v1(98.02,56.6)
  BOTTOM w0.097: v1(137.2,52.61) 137.22,52.59 137.22,52.22 137.22,52.22 137.22,51.95 137.04,51.77 135.36,51.77 134.55,50.96 134.55,50.08 134.45,49.97 134.13,49.97 134.04,49.88 134.04,49.76 134.13,49.67 134.45,49.67 134.53,49.58 134.53,49.46 134.45,49.37 134.24,49.37 134.12,49.25 134.12,49.24 133.99,49.12 133.8,49.12 133.72,49.04 133.72,48.69 133.53,48.49 133.53,48.37 133.56,48.33 133.56,48.3 133.66,48.2 133.87,48.2 134.02,48.36 134.1,48.36 134.21,48.46 134.23,48.49 134.23,48.75 U201.T3 ; 137.37,67.78 137.48,67.66 137.48,67.45 138.58,66.35 138.58,66.1 138.71,65.97 139,65.97 139.1,65.87 139.1,65.73 139,65.63 138.67,65.63 138.58,65.55 138.58,65.42 138.67,65.33 138.98,65.33 139.1,65.21 139.1,65.04 138.98,64.92 138.32,64.92 138.2,64.8 138.2,64.05 138.32,63.92 139.23,63.92 139.33,63.82 139.33,63.67 139.23,63.57 138.12,63.57 138.01,63.46 138.01,63.35 138.13,63.23 138.45,63.23 138.57,63.11 138.57,62.93 138.45,62.81 v1(138.09,62.81) 137.8,62.52 136.98,62.52 136.97,62.53 136.07,62.53 134.86,63.75 134.86,64.41 133.97,65.3 133.97,66.91 133.84,67.03 v1(133.56,67.03)
  BOTTOM w0.2: v1(98.02,56.6) 97.82,56.6 97.69,56.73 97.69,57.2 97.82,57.33 98.37,57.33 98.49,57.2 98.49,57.16 98.62,57.04 98.62,56.64 98.72,56.54 99,56.54 99.1,56.64 99.1,56.87 99.42,57.19 99.59,57.19 99.72,57.06 99.72,56.05 99.82,55.95 100.09,55.95 100.19,56.05 100.19,57.17 100.28,57.27 100.59,57.27 100.69,57.17 100.69,56.05 100.8,55.95 101.12,55.95 101.21,56.04 101.21,56.39 101.22,56.41 101.22,56.55 101.32,56.65 105.16,56.65 106.31,55.5 106.41,55.5 106.42,55.49 125.62,55.49 125.64,55.48 126.67,55.48 127.01,55.13 127.56,55.13 127.65,55.22 127.65,55.65 127.73,55.73 127.75,55.73 127.79,55.77 128,55.77 128.12,55.65 128.12,55.46 128.25,55.34 128.42,55.34 128.72,55.64 128.72,55.77 128.38,56.11 128.38,56.29 128.64,56.54 128.82,56.54 129.1,56.26 129.34,56.26 129.69,56.61 130.45,56.61 130.45,56.64 130.46,56.65 130.49,56.65 130.89,57.05 132.66,57.05 132.79,57.17 132.79,57.57 132.98,57.76 133.24,57.76 v3(133.23,57.77)
M_MAA14: length 113.5
  TOP w0.097: 137.37,67.78 137.37,67.78 137.53,67.62 137.53,67.62 138.04,67.11 138.44,67.11 139.03,66.52 139.91,66.52 140.11,66.33 140.11,65.14 140.12,65.13 140.12,64.91 139.84,64.63 139.45,64.63 139.34,64.52 139.34,64.38 139.45,64.27 140.09,64.27 140.31,64.49 140.48,64.49 140.6,64.38 140.6,64.03 140.47,63.9 139.43,63.9 139.3,63.77 139.3,63.64 139.39,63.55 140.48,63.55 140.57,63.45 140.57,63.31 140.48,63.21 137.91,63.21 137.78,63.07 137.63,63.07 137.48,62.92 v1(137.38,62.92) 137.32,62.87 137.03,62.87 136.91,62.76 136.9,62.76 136.88,62.74 136.42,62.74 135.44,61.77 133.58,61.77 133.51,61.74 133.1,61.33 132.7,61.33 131.59,60.23 131.59,59.62 131.73,59.48 131.73,58.67 v1(131.78,58.62) 131.94,58.47 131.94,57.02 133.52,55.44 133.9,55.44 134.49,54.84 135,54.84 135.15,54.7 135.15,54.58 135.01,54.44 135.01,54.32 135.1,54.23 135.22,54.23 135.36,54.37 135.48,54.37 135.73,54.12 135.73,54.1 136.21,53.62 136.22,53.61 136.22,53.6 136.22,53.2 136.31,53.1 136.32,53.1 136.38,53.03 v1(136.59,53.03) ; v1(133.72,49.52) 133.72,49.52 134.16,49.08 U202.T7
  TOP w0.17: U1.G14 97.75,60.9 97.84,60.98 98.1,60.98 98.2,60.89 98.2,60.85 98.45,60.61 98.97,60.61 v1(98.97,60.6)
  BOTTOM w0.097: 137.37,48.81 137.33,48.85 137.33,48.99 137.46,49.12 137.61,49.12 137.94,49.45 137.94,49.57 138.13,49.76 138.13,49.76 138.25,49.88 138.25,49.89 138.44,50.07 139.53,50.07 139.62,50.17 139.62,50.31 139.53,50.41 138.74,50.41 138.64,50.51 138.64,50.64 138.74,50.73 139.17,50.73 139.25,50.82 139.25,50.95 139.17,51.04 138.89,51.04 138.81,51.13 138.81,51.25 138.89,51.34 139.61,51.34 v4(139.67,51.4) 139.67,51.54 139.54,51.67 139.5,51.67 139.41,51.76 139.41,51.89 139.5,51.98 139.78,51.98 139.96,52.16 139.96,52.4 139.12,53.23 138.45,53.23 138.05,52.83 137.71,52.83 137.7,52.84 137.61,52.84 137.41,53.03 136.66,53.03 136.78,52.91 136.78,52.73 136.66,52.6 136.19,52.6 136.17,52.63 136.17,52.89 136.08,52.98 136,52.98 135.88,52.85 135.88,52.73 135.75,52.6 135.6,52.6 135.51,52.52 135.51,52.39 135.6,52.3 136.94,52.3 137.02,52.23 137.02,52.07 136.96,52.01 135.17,52.01 135.04,51.88 135.04,51.87 135.05,51.87 135.05,51.74 134.96,51.66 134.84,51.66 134.83,51.66 134.71,51.66 134.55,51.5 134.55,51.38 134.55,51.28 134.45,51.18 134.16,51.18 133.98,51 133.98,50.73 134.1,50.6 134.13,50.6 134.26,50.48 134.26,50.3 134.13,50.17 133.84,50.17 133.72,50.05 133.72,49.52 v1(133.72,49.52) ; U402.T7 134.16,67.78 134.29,67.91 134.76,67.91 134.89,67.78 134.89,67.55 134.76,67.42 134.1,67.42 134.01,67.33 134.01,67.22 134.1,67.14 134.76,67.14 134.89,67.01 134.89,66.92 134.79,66.83 134.25,66.83 134.17,66.74 134.17,66.61 134.25,66.53 134.79,66.53 134.89,66.43 134.89,66.32 134.79,66.23 134.25,66.23 134.17,66.14 134.17,66.01 134.25,65.93 134.78,65.93 134.91,65.8 134.91,65.73 134.78,65.61 134.29,65.61 134.21,65.52 134.21,65.39 134.34,65.27 135.26,65.27 135.39,65.14 135.39,64.08 136.54,62.92 v1(137.38,62.92)
  BOTTOM w0.1: 136.66,53.03 v1(136.59,53.03)
  BOTTOM w0.2: v1(131.78,58.62) 131.79,58.63 131.86,58.63 131.89,58.6 131.89,58.31 131.76,58.19 131.34,58.19 131.25,58.27 131.25,58.61 131.12,58.73 130.93,58.73 130.75,58.55 130.75,58.45 130.65,58.35 130.6,58.35 130.6,58.34 108.95,58.34 108.95,58.35 108.77,58.35 108.62,58.49 108.62,58.67 108.39,58.91 108.28,58.91 108.16,58.78 108.16,58.42 108.07,58.34 107.81,58.34 107.73,58.42 107.73,58.56 107.6,58.69 107.4,58.69 107.28,58.56 107.28,58.47 107.15,58.35 106.8,58.35 106.38,58.77 106.38,58.84 106.5,58.97 106.99,58.97 107.12,59.09 107.12,59.44 106.99,59.56 106.78,59.56 106.78,59.57 106.72,59.57 106.54,59.76 106.33,59.76 106.2,59.63 106.2,59.37 106.06,59.23 105.88,59.23 105.75,59.35 105.75,59.67 105.62,59.8 105.33,59.8 105.25,59.71 105.25,59.6 105.25,59.17 105.09,59.02 104.87,59.02 104.77,59.12 104.77,59.7 104.67,59.8 104.24,59.8 104.15,59.71 104.15,59.12 104.05,59.02 103.72,59.02 103.62,59.12 103.62,59.7 103.52,59.8 103.17,59.8 103.07,59.7 103.07,59.21 102.97,59.11 102.74,59.11 102.52,59.34 102.52,59.34 102.3,59.56 102.3,60.05 102.14,60.21 101.51,60.21 101.31,60.41 101.11,60.41 100.99,60.28 100.99,59.62 100.91,59.55 100.72,59.55 100.22,60.05 100.22,60.3 100.34,60.42 100.54,60.42 100.64,60.53 100.64,60.76 100.56,60.85 99.69,60.85 99.56,60.73 99.56,60.59 99.44,60.47 99.07,60.47 98.97,60.57 v1(98.97,60.6)
M_MDA0: length 68.6
  TOP w0.099: 96.27,45.15 96.02,46.29 95.69,47.52 95.66,47.6 95.66,48.23 95.64,48.36 95.64,48.81 95.66,48.97 95.66,49.83 95.65,49.89 U1.K27
  TOP w0.12: 138.16,41.62 138.89,41.99 139.69,41.99 139.8,41.89 140.28,41.42 140.3,41.42 140.77,40.95 141.3,40.2 141.3,35.47 139.07,33.24 139.05,33.24 135.75,30.54 135.43,30.26 123.98,30.26 123.84,30.31 v4(123.13,30.71) 121.78,31.48 121.38,31.75 121.14,31.89 120.81,31.94 107.63,31.94 106.34,33.23 105.9,33.28 100.28,38.9 100.28,41.01 98.93,42.49 96.27,45.15
M_MDA1: length 67.5
  TOP w0.099: 96.46,45.35 96.46,47.09 95.86,47.68 95.86,48.42 95.84,48.44 95.84,48.73 96.15,49.05 U1.J29
  TOP w0.12: 96.46,45.35 98.2,43.62 98.36,43.62 100.68,41.3 100.68,39.06 106.06,33.67 106.45,33.67 107.79,32.33 121.76,32.33 122.1,32 v4(122.26,32) 122.71,32 124.05,30.65 135.22,30.65 135.4,30.76 136.98,32.06 137.38,32.38 137.69,32.63 138.91,33.63 140.91,35.63 140.91,40.04 140.38,40.58 140.38,40.78 140.13,41.02 139.96,41.17 138.11,41.17 137.73,41.55 137.73,42.05 137.37,42.41
M_MDA2: length 67.2
  TOP w0.1: 96.67,47.62 96.67,48.01 96.63,48.05 96.63,48.34 96.95,48.65 U1.H30
  TOP w0.12: U202.F2 138.16,40.58 138.33,40.41 139.59,40.41 139.84,40.16 139.93,40.16 140.1,39.98 140.39,39.98 140.52,39.85 140.52,39.58 140.42,39.48 140.07,39.48 139.88,39.28 139.88,39.16 139.98,39.06 140.37,39.06 140.52,38.91 140.52,38.66 140.42,38.55 140.13,38.55 140.01,38.44 140.01,38.2 140.13,38.08 140.42,38.08 140.52,37.98 140.52,35.8 139.95,35.23 139.95,35.23 139,34.28 139,34.28 138.69,33.97 138.03,33.97 137.84,33.77 137.84,33.6 137.89,33.55 137.89,33.41 137.69,33.21 137.55,33.21 137.5,33.26 137.33,33.26 137.03,32.96 137.03,32.65 136.85,32.48 136.54,32.48 135.11,31.04 124.22,31.04 122.53,32.73 107.95,32.73 106.62,34.06 106.22,34.06 101.07,39.22 101.07,41.46 100.63,41.9 v4(100.63,42.3) 100.96,42.63 100.96,42.81 100.54,43.23 100.37,43.23 100.01,42.87 99.66,42.87 99,43.53 98.97,43.53 98.6,43.9 98.34,43.9 96.67,45.56 96.67,47.62
M_MDA3: length 63.9
  TOP w0.1: U1.H32 96.95,47.4
  TOP w0.12: v1(118.22,35.15) 123.48,35.15 125.24,33.4 134.12,33.4 136.46,35.73 136.46,35.76 136.46,35.77 136.46,36.85 136.57,36.97 136.95,36.97 137.07,37.09 137.07,37.38 136.95,37.51 136.59,37.51 136.46,37.63 136.46,38.31 136.59,38.44 136.86,38.44 136.98,38.56 136.98,38.78 136.88,38.88 136.71,38.88 136.59,39.01 136.59,39.19 137.37,39.97 137.37,40.02 ; 96.95,47.4 96.95,47.22 96.94,47.21 96.94,45.89 97.5,45.33 v1(97.6,45.33)
  BOTTOM w0.12: v1(97.6,45.33) 97.56,45.33 97.45,45.23 97.45,44.65 104.19,37.91 106.09,37.91 106.85,37.14 106.86,37.14 107.53,36.47 107.53,35.91 110.08,33.37 115.15,33.37 115.15,33.37 115.56,33.37 116.5,32.42 v4(119.02,32.42) 119.14,32.42 119.62,31.94 120.12,31.94 120.24,32.06 120.24,32.22 120.04,32.42 119.87,32.42 119.71,32.58 119.71,32.76 120.09,33.13 120.09,33.3 119.92,33.47 119.75,33.47 119.46,33.18 119.28,33.18 119.14,33.33 119.14,33.55 119.41,33.81 119.41,33.98 118.24,35.15 v1(118.22,35.15)
